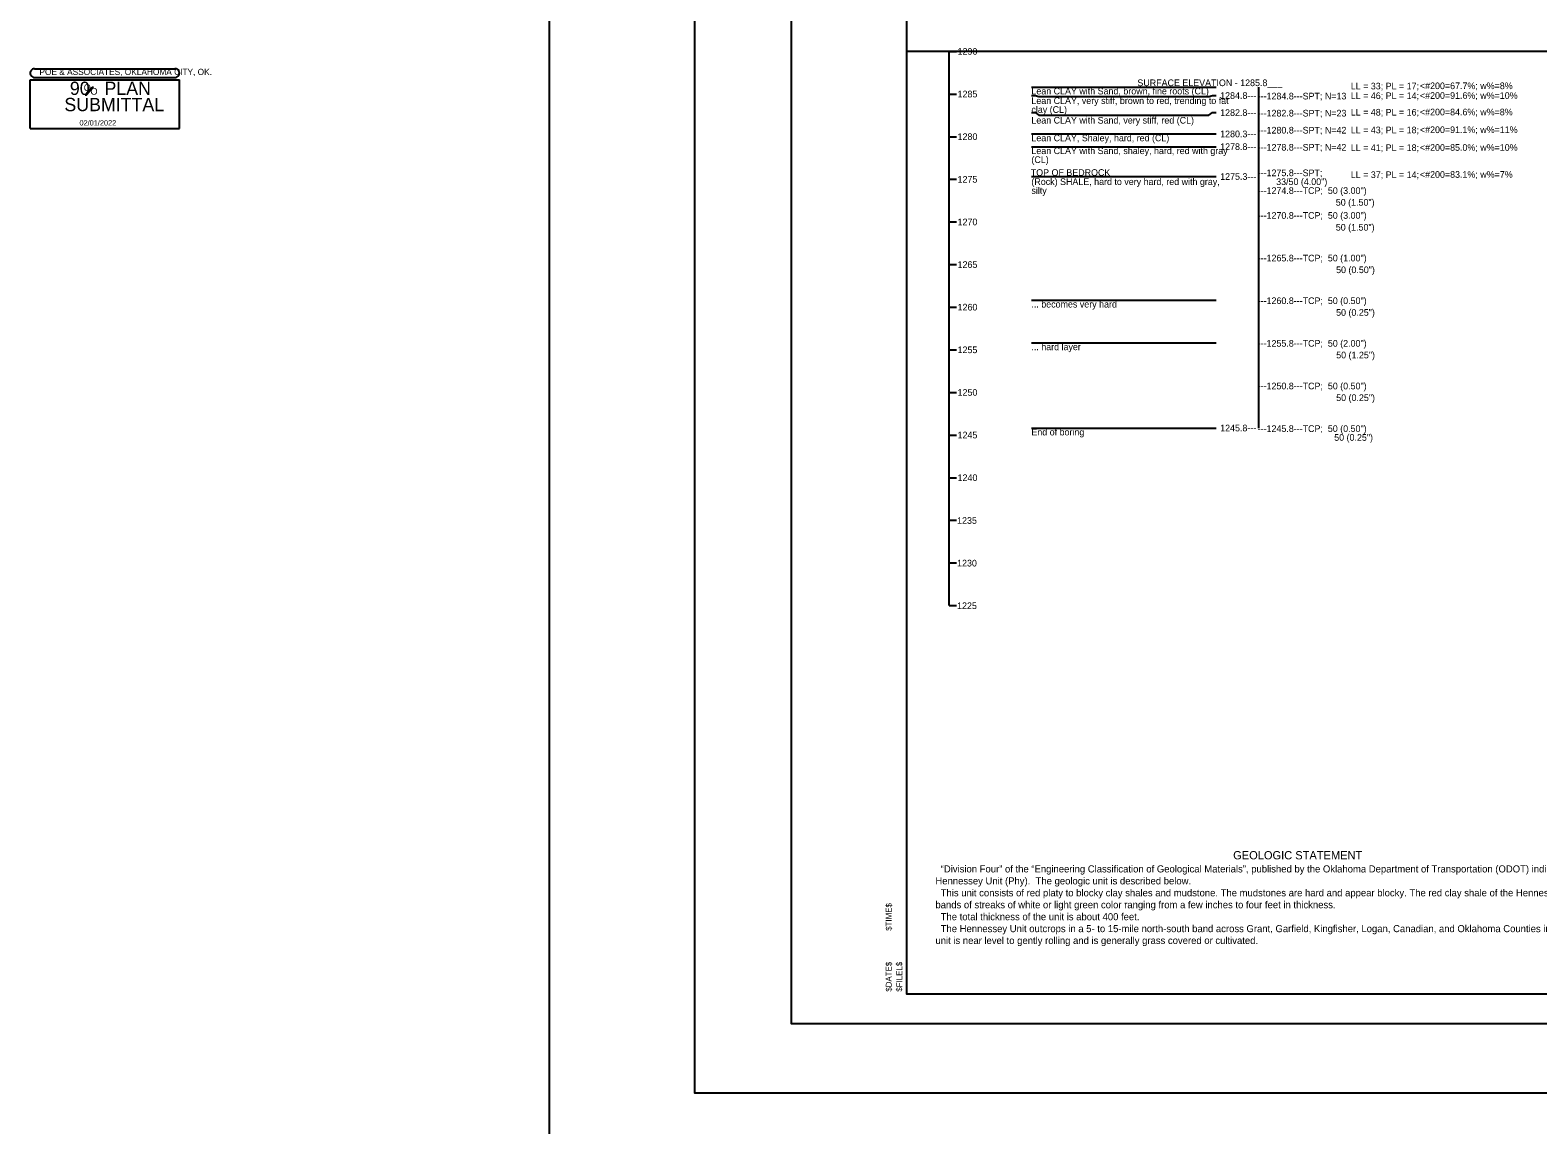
# Model space of a CAD drawing. Extents: x 2150148.6 to 2150220.1, y 143803.7 to 143875.1.
# Drawn here: x 2150148.61 to 2150182.61, y 143834.87 to 143859.57 of the extents above; entities that cross this region are included whole.
import ezdxf

# ---------------------------------------------------------------- set-up
doc = ezdxf.new("R2010")
doc.units = 0
for name, color, linetype in [('Default', 7, 'Continuous'), ('S', 7, 'Continuous'), ('SHT_Plot_Shape_Full', 7, 'Continuous'), ('SHT_Plot_Shape_Half', 7, 'Continuous'), ('SHT_Plot_Stamp', 7, 'Continuous'), ('SHT_Sheet_Border', 7, 'Continuous'), ('SHT_Stamp_90_Submit', 7, 'Continuous'), ('SHT_Stamp_Rev_Prop_RW', 7, 'Continuous'), ('Text', 7, 'Continuous')]:
    doc.layers.add(name, color=color, linetype=linetype)

# ---------------------------------------------------------------- blocks, each defined once
blk = doc.blocks.new('Stamp_Plot_Stamp')
at = {"layer": 'SHT_Plot_Stamp'}
for s, p in [('$TIME$', (1.695, 1.572)), ('$DATE$', (1.695, 0.542)), ('$FILEL$', (1.873, 0.542))]:
    blk.add_text(s, height=0.1, rotation=90, dxfattribs=at).set_placement(p)

msp = doc.modelspace()

# ---------------------------------------------------------------- linework, layer by layer
at = {"layer": 'Default'}
msp.add_line((2150169.335, 143846.586), (2150169.335, 143859.086), dxfattribs=at)
for points in [[(2150169.335, 143859.086), (2150169.501, 143859.086)], [(2150169.335, 143858.124), (2150169.501, 143858.124)], [(2150171.191, 143858.283), (2150175.358, 143858.283)], [(2150171.191, 143858.091), (2150171.274, 143858.091), (2150171.358, 143858.066), (2150175.191, 143858.066), (2150175.274, 143858.091), (2150175.358, 143858.091)], [(2150176.311, 143858.282), (2150176.311, 143850.591)], [(2150171.191, 143857.706), (2150171.274, 143857.706), (2150171.358, 143857.65), (2150175.191, 143857.65), (2150175.274, 143857.706), (2150175.358, 143857.706)], [(2150169.335, 143857.163), (2150169.501, 143857.163)], [(2150171.191, 143857.225), (2150175.358, 143857.225)], [(2150171.191, 143856.937), (2150175.358, 143856.937)], [(2150171.191, 143856.264), (2150175.358, 143856.264)], [(2150169.335, 143856.201), (2150169.501, 143856.201)], [(2150169.335, 143855.24), (2150169.501, 143855.24)], [(2150169.335, 143854.278), (2150169.501, 143854.278)], [(2150169.335, 143853.317), (2150169.501, 143853.317)], [(2150171.191, 143853.475), (2150175.358, 143853.475)], [(2150169.335, 143852.355), (2150169.501, 143852.355)], [(2150171.191, 143852.514), (2150175.358, 143852.514)], [(2150169.335, 143851.394), (2150169.501, 143851.394)], [(2150171.191, 143850.591), (2150175.358, 143850.591)], [(2150169.335, 143850.432), (2150169.501, 143850.432)], [(2150169.335, 143850.432), (2150169.501, 143850.432)], [(2150169.335, 143849.47), (2150169.501, 143849.47)], [(2150169.335, 143849.47), (2150169.501, 143849.47)], [(2150169.335, 143848.509), (2150169.501, 143848.509)], [(2150169.335, 143848.509), (2150169.501, 143848.509)], [(2150169.335, 143847.547), (2150169.501, 143847.547)], [(2150169.335, 143846.586), (2150169.501, 143846.586)]]:
    msp.add_lwpolyline(points, dxfattribs=at)
at = {"layer": 'Defpoints'}
msp.add_line((2150210.379, 143859.086), (2150168.379, 143859.086), dxfattribs=at)
at = {"layer": 'S'}
msp.add_lwpolyline([(2150160.321, 143875.14), (2150220.06, 143875.14), (2150220.06, 143803.708), (2150160.321, 143803.708)], close=True, dxfattribs=at)
at = {"layer": 'SHT_Plot_Shape_Full'}
msp.add_lwpolyline([(2150163.596, 143867.587), (2150211.596, 143867.587), (2150211.596, 143835.587), (2150163.596, 143835.587)], close=True, dxfattribs=at)
at = {"layer": 'SHT_Plot_Shape_Half'}
msp.add_lwpolyline([(2150165.779, 143866.487), (2150211.112, 143866.487), (2150211.112, 143837.154), (2150165.779, 143837.154)], close=True, dxfattribs=at)
at = {"layer": 'SHT_Sheet_Border'}
msp.add_lwpolyline([(2150210.379, 143837.82), (2150168.379, 143837.82), (2150168.379, 143865.82), (2150210.379, 143865.82)], close=True, dxfattribs=at)
at = {"layer": 'SHT_Stamp_90_Submit'}
for p, q in [((2150148.706, 143858.696), (2150151.872, 143858.696)), ((2150148.606, 143858.446), (2150151.972, 143858.446)), ((2150148.606, 143857.347), (2150148.606, 143858.446)), ((2150148.706, 143858.496), (2150151.872, 143858.496)), ((2150151.972, 143857.347), (2150151.972, 143858.446)), ((2150149.85, 143858.108), (2150150.005, 143858.281)), ((2150149.85, 143858.108), (2150149.88, 143858.108)), ((2150149.867, 143858.108), (2150150.023, 143858.281)), ((2150149.872, 143858.108), (2150150.028, 143858.281)), ((2150149.88, 143858.108), (2150150.036, 143858.281)), ((2150150.005, 143858.281), (2150150.036, 143858.281)), ((2150148.606, 143857.347), (2150151.972, 143857.347))]:
    msp.add_line(p, q, dxfattribs=at)
for centre, start, end in [((2150148.707, 143858.596), 89.9952, 270), ((2150151.873, 143858.596), 270, 90.0048)]:
    msp.add_arc(centre, 0.1, start, end, dxfattribs=at)

# ---------------------------------------------------------------- block references
at = {"layer": 'SHT_Plot_Stamp', "xscale": 1.3333300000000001, "yscale": 1.3333300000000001}
msp.add_blockref('Stamp_Plot_Stamp', (2150165.779, 143837.154), dxfattribs=at)

# ---------------------------------------------------------------- texts
at = {"layer": 'Default'}
for s, p in [('1290', (2150169.526, 143859.011)), ('SURFACE ELEVATION - 1285.8___', (2150173.582, 143858.303)), ('LL = 33; PL = 17;', (2150178.395, 143858.229)), ('<#200=67.7%; w%=8%', (2150179.955, 143858.235)), ('1285', (2150169.526, 143858.049)), ('Lean CLAY with Sand, brown, fine roots (CL)', (2150171.191, 143858.116)), ('Lean CLAY, very stiff, brown to red, trending to fat', (2150171.191, 143857.9)), ('1284.8---', (2150175.449, 143858.016)), ('---1284.8---SPT; N=13', (2150176.295, 143858.003)), ('LL = 46; PL = 14;', (2150178.395, 143858.011)), ('<#200=91.6%; w%=10%', (2150179.955, 143858.016)), ('clay (CL)', (2150171.191, 143857.7)), ('1282.8---', (2150175.449, 143857.631)), ('---1282.8---SPT; N=23', (2150176.295, 143857.618)), ('LL = 48; PL = 16;', (2150178.395, 143857.639)), ('<#200=84.6%; w%=8%', (2150179.955, 143857.644)), ('Lean CLAY with Sand, very stiff, red (CL)', (2150171.191, 143857.458)), ('1280.3---', (2150175.449, 143857.15)), ('---1280.8---SPT; N=42', (2150176.295, 143857.234)), ('LL = 43; PL = 18;', (2150178.395, 143857.239)), ('<#200=91.1%; w%=11%', (2150179.955, 143857.244)), ('1280', (2150169.526, 143857.088)), ('Lean CLAY, Shaley, hard, red (CL)', (2150171.191, 143857.059)), ('1278.8---', (2150175.449, 143856.862)), ('---1278.8---SPT; N=42', (2150176.295, 143856.849)), ('LL = 41; PL = 18;', (2150178.395, 143856.839)), ('<#200=85.0%; w%=10%', (2150179.955, 143856.844)), ('(CL)', (2150171.191, 143856.57)), ('Lean CLAY with Sand, shaley, hard, red with gray', (2150171.191, 143856.77)), ('1275', (2150169.526, 143856.126)), ('TOP OF BEDROCK', (2150171.177, 143856.279)), ('1275.3---', (2150175.449, 143856.189)), ('---1275.8---SPT;', (2150176.295, 143856.272)), ('LL = 37; PL = 14;', (2150178.395, 143856.229)), ('<#200=83.1%; w%=7%', (2150179.955, 143856.235)), ('silty', (2150171.191, 143855.873)), ('(Rock) SHALE, hard to very hard, red with gray,', (2150171.191, 143856.073)), ('---1274.8---TCP;  50 (3.00")', (2150176.295, 143855.872)), ('33/50 (4.00")', (2150176.712, 143856.072)), ('50 (1.50")', (2150178.057, 143855.606)), ('1270', (2150169.526, 143855.165)), ('---1270.8---TCP;  50 (3.00")', (2150176.295, 143855.311)), ('50 (1.50")', (2150178.057, 143855.044)), ('1265', (2150169.526, 143854.203)), ('---1265.8---TCP;  50 (1.00")', (2150176.295, 143854.349)), ('50 (0.50")', (2150178.064, 143854.085)), ('---1260.8---TCP;  50 (0.50")', (2150176.295, 143853.387)), ('1260', (2150169.526, 143853.242)), ('... becomes very hard', (2150171.191, 143853.309)), ('50 (0.25")', (2150178.064, 143853.123)), ('---1255.8---TCP;  50 (2.00")', (2150176.295, 143852.426)), ('1255', (2150169.526, 143852.28)), ('... hard layer', (2150171.191, 143852.347)), ('50 (1.25")', (2150178.066, 143852.162)), ('---1250.8---TCP;  50 (0.50")', (2150176.295, 143851.464)), ('1250', (2150169.526, 143851.319)), ('50 (0.25")', (2150178.066, 143851.2)), ('1245', (2150169.526, 143850.357)), ('End of boring', (2150171.191, 143850.424)), ('1245.8---', (2150175.449, 143850.516)), ('---1245.8---TCP;  50 (0.50")', (2150176.295, 143850.503)), ('50 (0.25")', (2150178.021, 143850.303)), ('1240', (2150169.526, 143849.395))]:
    msp.add_text(s, height=0.15, dxfattribs=at).set_placement(p)
for s, p in [('1235', (2150169.515, 143848.43)), ('1230', (2150169.515, 143847.468)), ('1225', (2150169.515, 143846.507))]:
    msp.add_text(s, height=0.15, rotation=0.0001, dxfattribs=at).set_placement(p)
at = {"layer": 'SHT_Stamp_90_Submit'}
for s, height, p in [('POE & ASSOCIATES, OKLAHOMA CITY, OK.', 0.14, (2150148.816, 143858.554)), ('90   PLAN', 0.3, (2150149.502, 143858.104)), ('O', 0.153, (2150149.815, 143858.193)), ('SUBMITTAL', 0.3, (2150149.378, 143857.738)), ('O', 0.153, (2150149.967, 143858.109))]:
    msp.add_text(s, height=height, dxfattribs=at).set_placement(p)
at = {"layer": 'SHT_Stamp_Rev_Prop_RW'}
msp.add_text('02/01/2022', height=0.12, dxfattribs=at).set_placement((2150149.719, 143857.415))
at = {"layer": 'Text'}
for s, height, p in [('GEOLOGIC STATEMENT', 0.18667, (2150175.742, 143840.861)), ('  “Division Four” of the “Engineering Classification of Geological Materials”, published by the Oklahoma Department of Transportation (ODOT) indicates that the site is underlain by the ', 0.159999, (2150169.026, 143840.566)), ('Hennessey Unit (Phy).  The geologic unit is described below. ', 0.16, (2150169.026, 143840.296)), ('  This unit consists of red platy to blocky clay shales and mudstone. The mudstones are hard and appear blocky. The red clay shale of the Hennessey Unit is characterized by numerous ', 0.159999, (2150169.026, 143840.027)), ('bands of streaks of white or light green color ranging from a few inches to four feet in thickness. ', 0.16, (2150169.026, 143839.758)), ('  The total thickness of the unit is about 400 feet.', 0.16, (2150169.026, 143839.488)), ('  The Hennessey Unit outcrops in a 5- to 15-mile north-south band across Grant, Garfield, Kingfisher, Logan, Canadian, and Oklahoma Counties in Division Four. Topographically, the ', 0.159999, (2150169.026, 143839.219)), ('unit is near level to gently rolling and is generally grass covered or cultivated.', 0.16, (2150169.026, 143838.952))]:
    msp.add_text(s, height=height, dxfattribs=at).set_placement(p)

doc.saveas('drawing.dxf')
